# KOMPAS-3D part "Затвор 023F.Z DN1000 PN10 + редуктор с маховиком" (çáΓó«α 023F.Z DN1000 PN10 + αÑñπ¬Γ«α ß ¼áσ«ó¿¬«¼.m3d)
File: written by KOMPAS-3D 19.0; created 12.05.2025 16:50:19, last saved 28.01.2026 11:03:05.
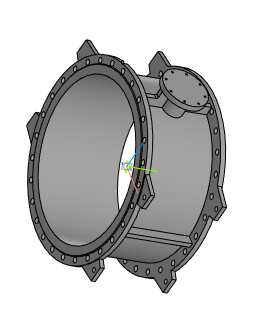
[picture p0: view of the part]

Document properties: Полное имя файла: Затвор 023F.Z DN1000 PN10 + редуктор с маховиком.a3d

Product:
- Part/product: Затвор 023F.Z DN1000 PN10 + редуктор с маховиком
    Масса: 1318.26
  - Body: Тело 1
      Масса: 680.724

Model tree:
1. Операция без истории:1
2. Эскиз:1  (with: Операция без истории:1)
3. Элемент выдавливания:1
     Расстояние 2 = 873
4. Эскиз:2  (with: Операция без истории:1)
5. Элемент выдавливания:2
     Расстояние 2 = 148
6. Эскиз:3  (with: Операция без истории:1)
7. Элемент выдавливания:3
     Расстояние 2 = 52
8. Элемент выдавливания:4
     Расстояние 2 = 380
